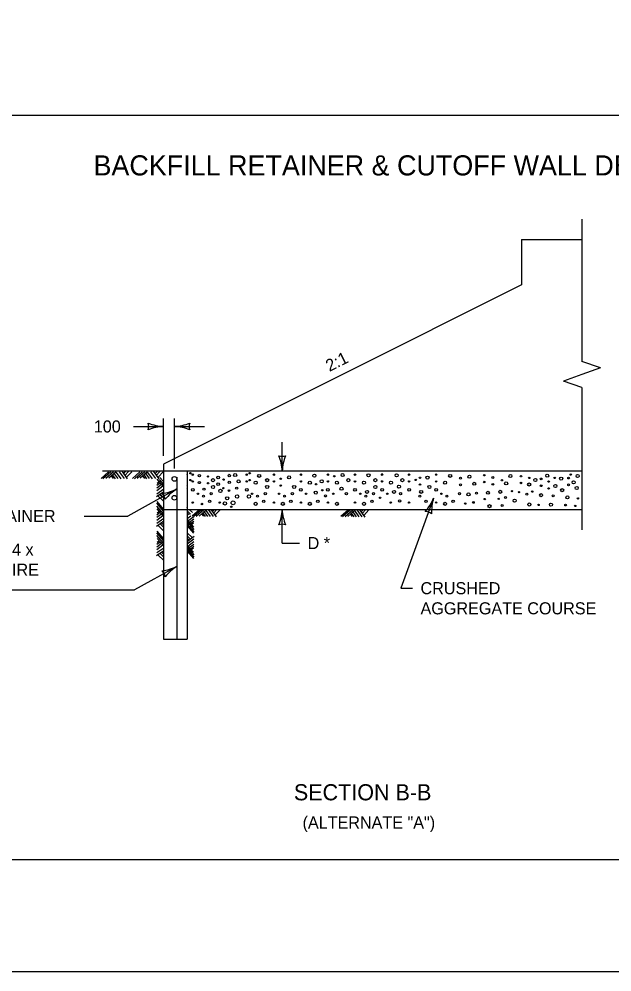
# Model space of a CAD drawing. Extents: x 49991.4 to 50021, y 49987.6 to 50011.4.
# Drawn here: x 50003.932 to 50006.879, y 49987.799 to 49992.532 of the extents above; entities that cross this region are included whole.
import ezdxf

# ---------------------------------------------------------------- set-up
doc = ezdxf.new("R2010")
doc.units = 0
for name, color, linetype in [('Level 1', 7, 'Continuous'), ('Level 2', 7, 'Continuous'), ('Level 3', 7, 'Continuous'), ('Level 6', 7, 'Continuous')]:
    doc.layers.add(name, color=color, linetype=linetype)

msp = doc.modelspace()

# ---------------------------------------------------------------- linework, layer by layer
at = {"layer": 'Level 1'}
for p, q in [((50006.4298, 49991.4374), (50006.4298, 49991.2116)), ((50006.4298, 49991.4374), (50006.7295, 49991.4374)), ((50006.4298, 49991.2116), (50004.65, 49990.3217)), ((50004.3766, 49990.2827), (50004.3396, 49990.2505)), ((50004.3459, 49990.287), (50004.767, 49990.287)), ((50004.3875, 49990.2827), (50004.3486, 49990.2488)), ((50004.4013, 49990.2829), (50004.3633, 49990.2498)), ((50004.4145, 49990.2831), (50004.3782, 49990.2515)), ((50004.4293, 49990.2835), (50004.4538, 49990.2498)), ((50004.4436, 49990.2837), (50004.4696, 49990.248)), ((50004.4506, 49990.2722), (50004.4614, 49990.2837)), ((50004.4571, 49990.2654), (50004.4754, 49990.2847)), ((50004.4666, 49990.2563), (50004.492, 49990.2833)), ((50004.533, 49990.2827), (50004.4959, 49990.2505)), ((50004.5439, 49990.2827), (50004.505, 49990.2488)), ((50004.5577, 49990.2829), (50004.5196, 49990.2498)), ((50004.5709, 49990.2831), (50004.5344, 49990.2515)), ((50004.5855, 49990.2835), (50004.6101, 49990.2498)), ((50004.5998, 49990.2837), (50004.626, 49990.248)), ((50004.6069, 49990.2722), (50004.6177, 49990.2837)), ((50004.6134, 49990.2654), (50004.6316, 49990.2847)), ((50004.623, 49990.2563), (50004.6484, 49990.2833)), ((50004.65, 49990.3217), (50004.65, 49989.4513)), ((50004.65, 49990.2827), (50004.65, 49990.2827)), ((50004.767, 49990.287), (50004.767, 49989.4513)), ((50004.767, 49990.287), (50006.7295, 49990.287)), ((50004.767, 49990.2827), (50004.767, 49990.2827)), ((50004.391, 49990.2621), (50004.3995, 49990.2504)), ((50004.3972, 49990.266), (50004.4097, 49990.2488)), ((50004.405, 49990.2732), (50004.4223, 49990.2494)), ((50004.4146, 49990.2797), (50004.4372, 49990.2488)), ((50004.5474, 49990.2621), (50004.5559, 49990.2504)), ((50004.5536, 49990.266), (50004.5661, 49990.2488)), ((50004.5613, 49990.2732), (50004.5787, 49990.2494)), ((50004.5709, 49990.2797), (50004.5934, 49990.2488)), ((50004.6504, 49990.2092), (50004.6188, 49990.2456)), ((50004.6502, 49990.2216), (50004.6297, 49990.2451)), ((50004.65, 49990.2344), (50004.6318, 49990.2553)), ((50004.7168, 49990.257), (50004.7168, 49989.4513)), ((50004.6332, 49990.227), (50004.6161, 49990.2144)), ((50004.647, 49990.211), (50004.6161, 49990.1885)), ((50004.6404, 49990.2198), (50004.6166, 49990.2025)), ((50004.6507, 49990.1973), (50004.6171, 49990.1727)), ((50004.6293, 49990.2326), (50004.6177, 49990.2241)), ((50004.651, 49990.1839), (50004.6153, 49990.1579)), ((50004.6236, 49990.1623), (50004.6504, 49990.1369)), ((50004.6327, 49990.1711), (50004.652, 49990.1527)), ((50004.6334, 49990.1694), (50004.6448, 49990.1586)), ((50004.6395, 49990.1768), (50004.6509, 49990.166)), ((50004.65, 49990.0879), (50004.6161, 49990.1268)), ((50004.6502, 49990.0749), (50004.6171, 49990.113)), ((50004.65, 49990.0982), (50004.6177, 49990.1352)), ((50004.6504, 49990.0627), (50004.6188, 49990.0991)), ((50004.65, 49990.0955), (50006.7295, 49990.0955)), ((50004.7934, 49990.0801), (50004.7771, 49990.0955)), ((50004.829, 49990.0944), (50004.792, 49990.0621)), ((50004.8388, 49990.0944), (50004.7999, 49990.0604)), ((50004.8511, 49990.0945), (50004.813, 49990.0614)), ((50004.8627, 49990.0948), (50004.8263, 49990.063)), ((50004.8725, 49990.0951), (50004.897, 49990.0615)), ((50004.8851, 49990.0953), (50004.9112, 49990.0597)), ((50004.8922, 49990.0839), (50004.903, 49990.0953)), ((50004.8976, 49990.077), (50004.9151, 49990.0955)), ((50004.9057, 49990.0678), (50004.9312, 49990.0948)), ((50005.59, 49990.0931), (50005.5519, 49990.06)), ((50005.6016, 49990.0934), (50005.5652, 49990.0616)), ((50005.6114, 49990.0937), (50005.636, 49990.0601)), ((50005.6242, 49990.0939), (50005.6502, 49990.0583)), ((50005.6312, 49990.0825), (50005.642, 49990.0939)), ((50005.6365, 49990.0756), (50005.6549, 49990.095)), ((50005.6447, 49990.0664), (50005.6701, 49990.0934)), ((50004.6332, 49990.0805), (50004.6161, 49990.0679)), ((50004.647, 49990.0644), (50004.6161, 49990.0418)), ((50004.6404, 49990.0733), (50004.6166, 49990.056)), ((50004.6507, 49990.0507), (50004.6171, 49990.0262)), ((50004.6293, 49990.0861), (50004.6177, 49990.0776)), ((50004.7842, 49990.0731), (50004.767, 49990.0894)), ((50004.7774, 49990.0687), (50004.767, 49990.0786)), ((50004.767, 49990.0508), (50004.7859, 49990.0646)), ((50004.77, 49990.0388), (50004.8008, 49990.0613)), ((50004.7766, 49990.0316), (50004.8003, 49990.0489)), ((50004.8393, 49990.0737), (50004.8478, 49990.0621)), ((50004.8447, 49990.0776), (50004.8572, 49990.0604)), ((50004.8513, 49990.0848), (50004.8686, 49990.061)), ((50004.8596, 49990.0914), (50004.8821, 49990.0605)), ((50005.5679, 49990.093), (50005.5309, 49990.0607)), ((50005.5777, 49990.093), (50005.5388, 49990.059)), ((50005.5783, 49990.0723), (50005.5867, 49990.0607)), ((50005.5836, 49990.0762), (50005.5961, 49990.059)), ((50005.5902, 49990.0834), (50005.6076, 49990.0596)), ((50005.5985, 49990.09), (50005.621, 49990.0591)), ((50004.651, 49990.0374), (50004.6153, 49990.0113)), ((50004.6236, 49990.0158), (50004.6504, 49989.9903)), ((50004.6327, 49990.0244), (50004.652, 49990.0062)), ((50004.6395, 49990.0303), (50004.6509, 49990.0195)), ((50004.767, 49990.044), (50004.7982, 49990.0082)), ((50004.767, 49990.034), (50004.7998, 49989.9962)), ((50004.767, 49990.0232), (50004.8008, 49989.9845)), ((50004.767, 49990.0143), (50004.7992, 49989.9774)), ((50004.7838, 49990.0259), (50004.8008, 49990.0383)), ((50004.7876, 49990.0213), (50004.7992, 49990.0298)), ((50004.65, 49989.9414), (50004.6161, 49989.9803)), ((50004.6502, 49989.9284), (50004.6171, 49989.9665)), ((50004.65, 49989.9517), (50004.6177, 49989.9887)), ((50004.6504, 49989.9162), (50004.6188, 49989.9525)), ((50004.7934, 49989.9551), (50004.767, 49989.98)), ((50004.7842, 49989.9482), (50004.767, 49989.9645)), ((50004.767, 49989.9374), (50004.8016, 49989.9626)), ((50004.7774, 49989.9438), (50004.767, 49989.9537)), ((50004.6332, 49989.9338), (50004.6161, 49989.9213)), ((50004.647, 49989.9179), (50004.6161, 49989.8953)), ((50004.6404, 49989.9267), (50004.6166, 49989.9093)), ((50004.6507, 49989.9042), (50004.6171, 49989.8797)), ((50004.6293, 49989.9396), (50004.6177, 49989.9311)), ((50004.767, 49989.9259), (50004.7998, 49989.9499)), ((50004.767, 49989.9191), (50004.7982, 49989.8832)), ((50004.767, 49989.9089), (50004.7998, 49989.8712)), ((50004.77, 49989.9138), (50004.8008, 49989.9363)), ((50004.7766, 49989.9066), (50004.8003, 49989.924)), ((50004.7838, 49989.9009), (50004.8008, 49989.9134)), ((50004.7876, 49989.8964), (50004.7992, 49989.9049)), ((50004.651, 49989.8909), (50004.6153, 49989.8648)), ((50004.6236, 49989.8693), (50004.6504, 49989.8437)), ((50004.6327, 49989.8779), (50004.652, 49989.8597)), ((50004.6395, 49989.8838), (50004.6509, 49989.873)), ((50004.767, 49989.8983), (50004.8008, 49989.8594)), ((50004.767, 49989.8894), (50004.7992, 49989.8523)), ((50004.65, 49989.6899), (50004.65, 49989.6899)), ((50004.65, 49989.4513), (50004.767, 49989.4513))]:
    msp.add_line(p, q, dxfattribs=at)
for points in [[(49999.3835, 49998.9992), (50016.7501, 49998.9992), (50016.7501, 49987.7988), (49999.3835, 49987.7988)], [(49999.5613, 49992.0549), (50014.5211, 49992.0549), (50014.5211, 49988.3552), (49999.5613, 49988.3552)]]:
    msp.add_lwpolyline(points, close=True, dxfattribs=at)
for centre, radius in [((50004.7044, 49990.2475), 0.0116), ((50004.7838, 49990.2758), 0.00346), ((50004.7838, 49990.242), 0.00346), ((50004.795, 49990.2688), 0.00341), ((50004.795, 49990.2351), 0.00341), ((50004.828, 49990.2634), 0.00552), ((50004.828, 49990.2296), 0.00552), ((50004.8714, 49990.2597), 0.00341), ((50004.896, 49990.2414), 0.00765), ((50004.9218, 49990.2553), 0.00684), ((50004.9481, 49990.2443), 0.00341), ((50004.9768, 49990.2644), 0.00613), ((50004.9768, 49990.2306), 0.00613), ((50005.0061, 49990.267), 0.00765), ((50005.0229, 49990.2353), 0.00765), ((50005.0638, 49990.2688), 0.00341), ((50005.0638, 49990.2351), 0.00341), ((50005.078, 49990.2758), 0.00346), ((50005.078, 49990.242), 0.00346), ((50005.1082, 49990.229), 0.00766), ((50005.1251, 49990.2627), 0.00766), ((50005.1649, 49990.2414), 0.00765), ((50005.1983, 49990.2688), 0.00341), ((50005.1983, 49990.2351), 0.00341), ((50005.2323, 49990.2484), 0.00346), ((50005.274, 49990.2554), 0.00765), ((50005.3327, 49990.2688), 0.00341), ((50005.3327, 49990.2351), 0.00341), ((50005.3771, 49990.229), 0.00766), ((50005.3996, 49990.2641), 0.00766), ((50005.4362, 49990.236), 0.00766), ((50005.4671, 49990.2688), 0.00341), ((50005.4671, 49990.2351), 0.00341), ((50005.4981, 49990.2611), 0.00341), ((50005.5115, 49990.229), 0.00766), ((50005.5397, 49990.267), 0.00766), ((50005.5682, 49990.2414), 0.00765), ((50005.6016, 49990.2688), 0.00341), ((50005.6016, 49990.2351), 0.00341), ((50005.646, 49990.229), 0.00766), ((50005.6685, 49990.2655), 0.00766), ((50005.7026, 49990.2414), 0.00765), ((50005.736, 49990.2688), 0.00341), ((50005.736, 49990.2351), 0.00341), ((50005.7804, 49990.229), 0.00766), ((50005.8085, 49990.2655), 0.00766), ((50005.8371, 49990.2414), 0.00765), ((50005.8704, 49990.2688), 0.00341), ((50005.8704, 49990.2351), 0.00341), ((50005.9032, 49990.2428), 0.00341), ((50005.9246, 49990.2532), 0.00341), ((50005.9617, 49990.254), 0.00765), ((50006.0049, 49990.2688), 0.00341), ((50006.0049, 49990.2351), 0.00341), ((50006.0493, 49990.229), 0.00766), ((50006.0746, 49990.2627), 0.00766), ((50006.1258, 49990.2517), 0.0046), ((50006.1702, 49990.2586), 0.00766), ((50006.2441, 49990.266), 0.00341), ((50006.2441, 49990.2323), 0.00341), ((50006.2863, 49990.2546), 0.0046), ((50006.3318, 49990.2409), 0.00341), ((50006.374, 49990.2621), 0.00766), ((50006.4265, 49990.2611), 0.00341), ((50006.4673, 49990.2527), 0.00341), ((50006.4979, 49990.2426), 0.00766), ((50006.5268, 49990.2476), 0.0046), ((50006.5568, 49990.2636), 0.00766), ((50006.564, 49990.2344), 0.00341), ((50006.5939, 49990.2527), 0.00341), ((50006.6261, 49990.2492), 0.00766), ((50006.6632, 49990.2521), 0.0046), ((50006.6736, 49990.269), 0.00341), ((50006.688, 49990.2309), 0.00766), ((50006.7077, 49990.2619), 0.00766), ((50004.795, 49990.1939), 0.00684), ((50004.8508, 49990.1968), 0.00552), ((50004.8714, 49990.2259), 0.00341), ((50004.896, 49990.2076), 0.00765), ((50004.9218, 49990.2215), 0.00684), ((50004.9325, 49990.1879), 0.00824), ((50004.9478, 49990.2017), 0.00341), ((50004.9754, 49990.1895), 0.0046), ((50005.0137, 49990.2017), 0.00552), ((50005.0638, 49990.1939), 0.00684), ((50005.1649, 49990.2076), 0.00765), ((50005.2323, 49990.2146), 0.00346), ((50005.2993, 49990.2076), 0.00765), ((50005.3327, 49990.1939), 0.00684), ((50005.4081, 49990.221), 0.00341), ((50005.439, 49990.1915), 0.00341), ((50005.4671, 49990.1939), 0.00684), ((50005.5344, 49990.1992), 0.00765), ((50005.6016, 49990.1939), 0.00684), ((50005.6613, 49990.1832), 0.00766), ((50005.7026, 49990.2076), 0.00765), ((50005.736, 49990.1939), 0.00684), ((50005.7957, 49990.1832), 0.00766), ((50005.8202, 49990.209), 0.00765), ((50005.8704, 49990.1939), 0.00684), ((50005.9246, 49990.2195), 0.00341), ((50005.9302, 49990.1832), 0.00766), ((50005.9715, 49990.2076), 0.00765), ((50006.0049, 49990.1939), 0.00684), ((50006.1258, 49990.2179), 0.0046), ((50006.1941, 49990.2235), 0.00766), ((50006.2863, 49990.2208), 0.0046), ((50006.3233, 49990.1834), 0.00766), ((50006.3529, 49990.2256), 0.00766), ((50006.3822, 49990.1868), 0.00341), ((50006.4265, 49990.2274), 0.00341), ((50006.467, 49990.2201), 0.00766), ((50006.4823, 49990.1846), 0.00341), ((50006.5268, 49990.2138), 0.0046), ((50006.564, 49990.2007), 0.00341), ((50006.5973, 49990.2129), 0.00766), ((50006.631, 49990.1918), 0.00766), ((50006.6632, 49990.2183), 0.0046), ((50006.7035, 49990.2028), 0.00766), ((50004.704, 49990.154), 0.0116), ((50004.821, 49990.174), 0.00341), ((50004.8486, 49990.1618), 0.0046), ((50004.8792, 49990.1359), 0.00613), ((50004.8868, 49990.174), 0.00552), ((50004.9662, 49990.1513), 0.00766), ((50005.0158, 49990.1603), 0.00824), ((50005.0745, 49990.1603), 0.00824), ((50005.0899, 49990.174), 0.00341), ((50005.1174, 49990.1618), 0.0046), ((50005.1481, 49990.1359), 0.00613), ((50005.1557, 49990.174), 0.00552), ((50005.2243, 49990.174), 0.00341), ((50005.2519, 49990.1618), 0.0046), ((50005.2825, 49990.1359), 0.00613), ((50005.2901, 49990.174), 0.00552), ((50005.3587, 49990.174), 0.00341), ((50005.4066, 49990.1797), 0.00766), ((50005.4169, 49990.1359), 0.00613), ((50005.4547, 49990.1634), 0.00552), ((50005.4932, 49990.174), 0.00341), ((50005.559, 49990.174), 0.00552), ((50005.6276, 49990.174), 0.00341), ((50005.6552, 49990.1618), 0.0046), ((50005.6858, 49990.1359), 0.00613), ((50005.6935, 49990.174), 0.00552), ((50005.7261, 49990.1544), 0.00341), ((50005.762, 49990.174), 0.00341), ((50005.8233, 49990.1382), 0.00552), ((50005.8279, 49990.174), 0.00552), ((50005.924, 49990.1618), 0.0046), ((50005.9547, 49990.1359), 0.00613), ((50006.0309, 49990.174), 0.00341), ((50006.0585, 49990.1618), 0.0046), ((50006.0891, 49990.1359), 0.00613), ((50006.1211, 49990.174), 0.00552), ((50006.1658, 49990.1707), 0.00766), ((50006.205, 49990.177), 0.0046), ((50006.2464, 49990.1472), 0.00341), ((50006.2619, 49990.1788), 0.00766), ((50006.3157, 49990.1488), 0.00341), ((50006.3494, 49990.1554), 0.0046), ((50006.3946, 49990.1394), 0.00766), ((50006.4162, 49990.1818), 0.00341), ((50006.4558, 49990.172), 0.0046), ((50006.5264, 49990.1668), 0.00766), ((50006.5861, 49990.164), 0.0046), ((50006.6574, 49990.156), 0.00766), ((50006.7095, 49990.1509), 0.00341), ((50004.795, 49990.1298), 0.00341), ((50004.8409, 49990.123), 0.00341), ((50004.9294, 49990.1298), 0.00341), ((50004.9547, 49990.1256), 0.00824), ((50004.9869, 49990.1096), 0.00341), ((50004.9955, 49990.1288), 0.00968), ((50005.1082, 49990.1237), 0.00766), ((50005.1983, 49990.1298), 0.00341), ((50005.2427, 49990.1237), 0.00766), ((50005.3327, 49990.1298), 0.00341), ((50005.3771, 49990.1237), 0.00766), ((50005.4671, 49990.1298), 0.00341), ((50005.5115, 49990.1237), 0.00766), ((50005.6016, 49990.1298), 0.00341), ((50005.646, 49990.1237), 0.00766), ((50005.779, 49990.1298), 0.00341), ((50005.8704, 49990.1298), 0.00341), ((50006.0049, 49990.1298), 0.00341), ((50006.0493, 49990.1237), 0.00766), ((50006.1497, 49990.1252), 0.00341), ((50006.1898, 49990.131), 0.0046), ((50006.2699, 49990.1122), 0.00766), ((50006.3325, 49990.1154), 0.0046), ((50006.4677, 49990.1206), 0.00766), ((50006.5141, 49990.1185), 0.00341), ((50006.5756, 49990.1199), 0.00766), ((50006.6484, 49990.1179), 0.0046), ((50006.6964, 49990.1138), 0.00341)]:
    msp.add_circle(centre, radius, dxfattribs=at)
for centre, radius, start, end in [((50004.7652, 49990.2685), 0.0031, 305.1264, 54.8736), ((50005.7358, 49990.2696), 0.00277, 77.9755, 102.0245), ((50005.7358, 49990.2358), 0.00277, 77.9755, 102.0245), ((50004.7616, 49990.2076), 0.00765, 314.8637, 45.1363), ((50004.7616, 49990.1023), 0.00765, 14.7763, 45.1363)]:
    msp.add_arc(centre, radius, start, end, dxfattribs=at)
at = {"layer": 'Level 3'}
for p, q in [((50004.65, 49990.3617), (50004.65, 49990.5483)), ((50004.7041, 49990.2991), (50004.7041, 49990.5483)), ((50004.5, 49990.5083), (50004.65, 49990.5083)), ((50004.7041, 49990.5083), (50004.8541, 49990.5083)), ((50005.2397, 49990.287), (50005.2397, 49990.4299)), ((50004.7168, 49990.1978), (50004.4725, 49990.0632)), ((50005.9923, 49990.1521), (50005.8298, 49989.7049)), ((50005.2397, 49989.929), (50005.2397, 49990.0955)), ((50004.256, 49990.0632), (50004.4725, 49990.0632)), ((50005.2397, 49989.929), (50005.3262, 49989.929)), ((50004.7168, 49989.8132), (50004.5053, 49989.6967)), ((50003.7476, 49989.6967), (50004.5053, 49989.6967)), ((50005.8298, 49989.7049), (50005.8872, 49989.7049))]:
    msp.add_line(p, q, dxfattribs=at)
for centre, radius, start, end in [((50004.6592, 49990.7305), 0.2223, 247.456, 267.6395), ((50004.5218, 49990.5083), 0.0548, 342.1388, 17.8612), ((50004.6926, 49990.741), 0.233, 272.8273, 292.0772), ((50004.8323, 49990.5083), 0.0548, 162.1388, 197.8612), ((50004.6615, 49990.2756), 0.233, 92.8273, 112.0772), ((50004.695, 49990.2862), 0.2223, 67.456, 87.6395), ((50005.2397, 49990.4152), 0.0548, 252.1388, 287.8612), ((50005.007, 49990.2755), 0.233, 2.8273, 22.0772), ((50005.4619, 49990.2779), 0.2223, 157.456, 177.6395), ((50004.6177, 49990.3968), 0.2223, 276.3053, 296.4888), ((50004.8392, 49989.9995), 0.233, 121.6766, 140.9265), ((50004.6045, 49990.1359), 0.0548, 10.9881, 46.7105), ((50005.7867, 49990.2366), 0.2223, 317.4863, 337.6698), ((50006.215, 49990.0835), 0.233, 162.8576, 182.1074), ((50005.0176, 49990.1047), 0.2223, 337.456, 357.6395), ((50005.4724, 49990.107), 0.233, 182.8273, 202.0772), ((50005.9485, 49990.0316), 0.0548, 52.1691, 87.8914), ((50005.2397, 49989.9673), 0.0548, 72.1388, 107.8612), ((50004.6177, 49990.0122), 0.2223, 276.3053, 296.4888), ((50004.8392, 49989.615), 0.233, 121.6766, 140.9265), ((50004.6045, 49989.7514), 0.0548, 10.9881, 46.7105)]:
    msp.add_arc(centre, radius, start, end, dxfattribs=at)
at = {"layer": 'Level 6'}
for p, q in [((50006.7295, 49991.5374), (50006.7295, 49990.8312)), ((50006.8209, 49990.7988), (50006.7295, 49990.8312)), ((50006.7295, 49990.7664), (50006.6381, 49990.734)), ((50006.8209, 49990.7988), (50006.7295, 49990.7664)), ((50006.7295, 49990.7016), (50006.6381, 49990.734)), ((50006.7295, 49990.7016), (50006.7295, 49989.9955))]:
    msp.add_line(p, q, dxfattribs=at)

# ---------------------------------------------------------------- texts
at = {"layer": 'Level 2'}
for s, height, p in [('BACKFILL RETAINER & CUTOFF WALL DETAIL', 0.1, (50004.3019, 49991.755)), ('100', 0.06, (50004.3035, 49990.4783)), ('BACKFILL RETAINER', 0.06, (50003.3063, 49990.0332)), ('D *', 0.06, (50005.3662, 49989.899)), ('152.4 x 152.4 x ', 0.06, (50003.4555, 49989.8667)), ('MW18.71 WIRE', 0.06, (50003.4555, 49989.7667)), ('CRUSHED ', 0.06, (50005.9272, 49989.6749)), ('AGGREGATE COURSE', 0.06, (50005.9272, 49989.5749)), ('SECTION B-B', 0.08, (50005.2977, 49988.6512)), ('(ALTERNATE "A")', 0.06, (50005.3409, 49988.5112))]:
    msp.add_text(s, height=height, dxfattribs=at).set_placement(p)
msp.add_text('2:1', height=0.06, rotation=26.5651, dxfattribs=at).set_placement((50005.4747, 49990.7788))

doc.saveas('drawing.dxf')
